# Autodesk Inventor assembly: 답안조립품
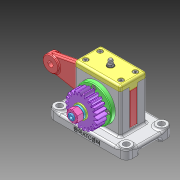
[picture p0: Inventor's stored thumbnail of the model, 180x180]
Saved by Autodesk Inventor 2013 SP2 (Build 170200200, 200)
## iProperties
Created: 2025-04
Part Number: 답안조립품
Document SubType Name: Assembly
Designer: 601
Author: 601
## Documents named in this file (15)
- C:\Users\601\Desktop\750404V1004\답안조립품.iam
- C:\Users\601\Desktop\750404V1004\본체.ipt
- C:\Users\601\Desktop\750404V1004\그리스 니플 M6x0.75.ipt
- C:\Users\601\Desktop\750404V1004\로드.ipt
- C:\Users\601\Desktop\750404V1004\스퍼기어.ipt
- C:\Users\601\Desktop\750404V1004\스프링와셔 M10.ipt
- C:\Users\601\Desktop\750404V1004\실링.ipt
- C:\Users\601\Desktop\750404V1004\앞커버.ipt
- C:\Users\601\Desktop\750404V1004\윗커버.ipt
- C:\Users\601\Desktop\750404V1004\육각 너트 M10.ipt
- C:\Users\601\Desktop\750404V1004\육각 소켓 머리 볼트 M4x10.ipt
- C:\Users\601\Desktop\750404V1004\편심축.ipt
- C:\Users\601\Desktop\750404V1004\평와셔 M10.ipt
- C:\Users\601\Desktop\750404V1004\평행키 4x4x10.ipt
- C:\Users\601\Desktop\750404V1004\플랜지 오일레스 부시.ipt
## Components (3 placed, 2 different names)
1. 그리스 니플 M6x0.75:1
2. 플랜지 오일레스 부시:1
3. 플랜지 오일레스 부시:2
